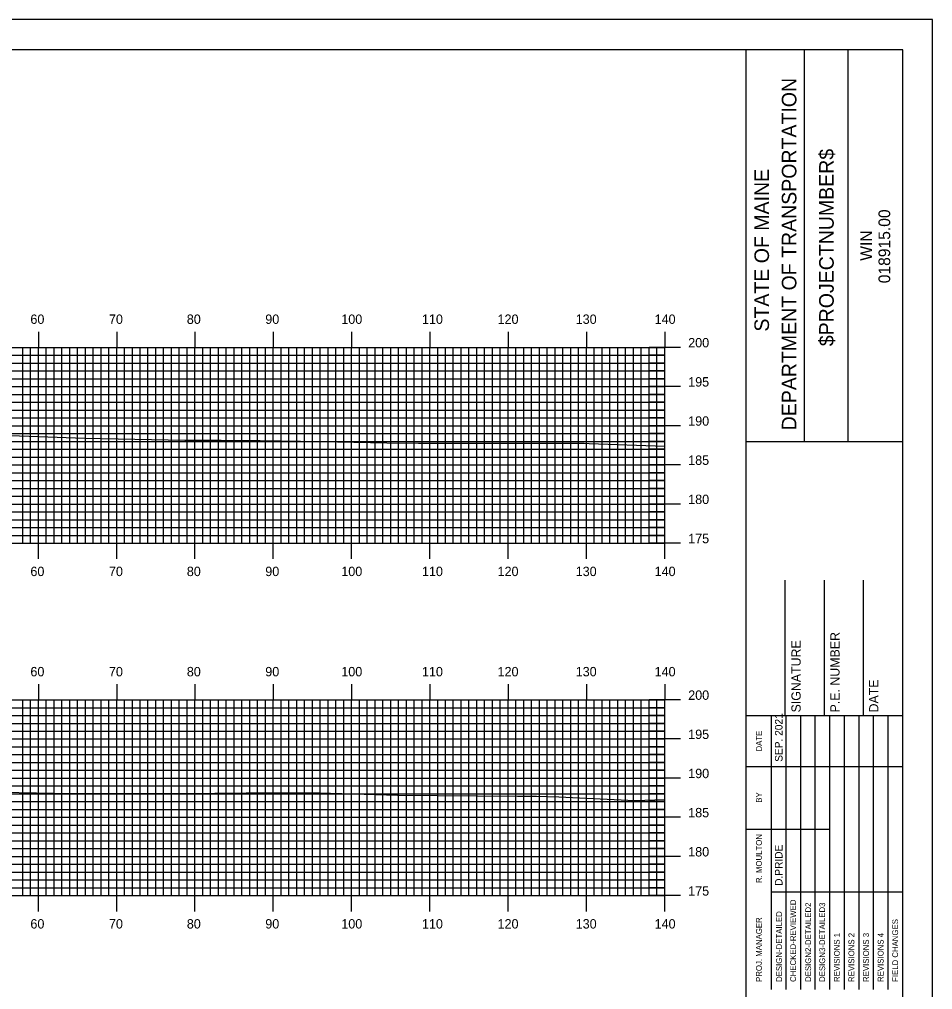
# Model space of a CAD drawing. Extents: x 1797601 to 1797944, y 442591 to 442811.
# Drawn here: x 1797824 to 1797940.7, y 442686.7 to 442810.5 of the extents above; entities that cross this region are included whole.
import ezdxf

# ---------------------------------------------------------------- set-up
doc = ezdxf.new("R2010")
doc.units = 0
for name, color, linetype in [('BORDER', 7, 'Continuous'), ('H_V ANNOTATION', 7, 'Continuous'), ('MAJOR', 7, 'Continuous'), ('MINOR', 7, 'Continuous'), ('PLOT BOUNDARY', 7, 'Continuous'), ('S_Roadway_Centerline', 7, 'Continuous')]:
    doc.layers.add(name, color=color, linetype=linetype)

msp = doc.modelspace()

# ---------------------------------------------------------------- linework, layer by layer
at = {"layer": 'BORDER'}
for p, q in [((1797916.84, 442596.67), (1797916.84, 442806.67)), ((1797924.3, 442756.66), (1797924.3, 442806.66)), ((1797929.89, 442756.66), (1797929.89, 442806.66)), ((1797916.85, 442756.65), (1797936.84, 442756.65)), ((1797921.84, 442721.67), (1797921.84, 442738.97)), ((1797926.84, 442721.67), (1797926.84, 442738.97)), ((1797931.84, 442721.67), (1797931.84, 442738.97)), ((1797916.84, 442721.67), (1797936.84, 442721.67))]:
    msp.add_line(p, q, dxfattribs=at)
msp.add_lwpolyline([(1797616.84, 442596.67), (1797936.84, 442596.67), (1797936.84, 442806.67), (1797616.84, 442806.67)], close=True, dxfattribs=at)
for points in [[(1797920.07, 442715.17), (1797920.07, 442721.67)], [(1797921.94, 442686.68), (1797921.94, 442721.67)], [(1797923.8, 442721.67), (1797923.8, 442686.68)], [(1797925.67, 442686.68), (1797925.67, 442721.67)], [(1797927.53, 442686.68), (1797927.53, 442721.67)], [(1797929.39, 442686.68), (1797929.39, 442721.67)], [(1797931.26, 442686.68), (1797931.26, 442721.67)], [(1797933.12, 442686.68), (1797933.12, 442721.67)], [(1797934.98, 442686.68), (1797934.98, 442721.67)], [(1797920.08, 442686.68), (1797920.08, 442720.26)], [(1797916.84, 442715.17), (1797936.84, 442715.17)], [(1797916.84, 442707.17), (1797920.08, 442707.17)], [(1797920.07, 442707.17), (1797927.53, 442707.17)], [(1797920.07, 442699.17), (1797936.84, 442699.17)]]:
    msp.add_lwpolyline(points, dxfattribs=at)
at = {"layer": 'MAJOR'}
for p, q in [((1797826.44, 442770.67), (1797826.44, 442768.67)), ((1797836.44, 442770.67), (1797836.44, 442768.67)), ((1797846.44, 442770.67), (1797846.44, 442768.67)), ((1797856.44, 442770.67), (1797856.44, 442768.67)), ((1797866.44, 442770.67), (1797866.44, 442768.67)), ((1797876.44, 442770.67), (1797876.44, 442768.67)), ((1797886.44, 442770.67), (1797886.44, 442768.67)), ((1797896.44, 442770.67), (1797896.44, 442768.67)), ((1797906.44, 442770.67), (1797906.44, 442768.67)), ((1797626.44, 442768.67), (1797906.44, 442768.67)), ((1797626.44, 442768.67), (1797906.44, 442768.67)), ((1797826.44, 442743.67), (1797826.44, 442768.67)), ((1797836.44, 442743.67), (1797836.44, 442768.67)), ((1797846.44, 442743.67), (1797846.44, 442768.67)), ((1797856.44, 442743.67), (1797856.44, 442768.67)), ((1797866.44, 442743.67), (1797866.44, 442768.67)), ((1797876.44, 442743.67), (1797876.44, 442768.67)), ((1797886.44, 442743.67), (1797886.44, 442768.67)), ((1797896.44, 442743.67), (1797896.44, 442768.67)), ((1797908.45, 442768.67), (1797904.44, 442768.67)), ((1797906.44, 442743.67), (1797906.44, 442768.67)), ((1797906.44, 442743.67), (1797906.44, 442768.67)), ((1797626.44, 442763.67), (1797906.44, 442763.67)), ((1797908.45, 442763.67), (1797904.44, 442763.67)), ((1797626.44, 442758.67), (1797906.44, 442758.67)), ((1797908.45, 442758.67), (1797904.44, 442758.67)), ((1797626.44, 442753.67), (1797906.44, 442753.67)), ((1797908.45, 442753.67), (1797904.44, 442753.67)), ((1797626.44, 442748.67), (1797906.44, 442748.67)), ((1797908.45, 442748.67), (1797904.44, 442748.67)), ((1797626.44, 442743.67), (1797906.44, 442743.67)), ((1797626.44, 442743.67), (1797906.44, 442743.67)), ((1797826.44, 442741.66), (1797826.44, 442743.67)), ((1797836.44, 442741.66), (1797836.44, 442743.67)), ((1797846.44, 442741.66), (1797846.44, 442743.67)), ((1797856.44, 442741.66), (1797856.44, 442743.67)), ((1797866.44, 442741.66), (1797866.44, 442743.67)), ((1797876.44, 442741.66), (1797876.44, 442743.67)), ((1797886.44, 442741.66), (1797886.44, 442743.67)), ((1797896.44, 442741.66), (1797896.44, 442743.67)), ((1797908.45, 442743.67), (1797904.44, 442743.67)), ((1797906.44, 442741.66), (1797906.44, 442743.67)), ((1797826.44, 442725.67), (1797826.44, 442723.67)), ((1797836.44, 442725.67), (1797836.44, 442723.67)), ((1797846.44, 442725.67), (1797846.44, 442723.67)), ((1797856.44, 442725.67), (1797856.44, 442723.67)), ((1797866.44, 442725.67), (1797866.44, 442723.67)), ((1797876.44, 442725.67), (1797876.44, 442723.67)), ((1797886.44, 442725.67), (1797886.44, 442723.67)), ((1797896.44, 442725.67), (1797896.44, 442723.67)), ((1797906.44, 442725.67), (1797906.44, 442723.67)), ((1797626.44, 442723.67), (1797906.44, 442723.67)), ((1797626.44, 442723.67), (1797906.44, 442723.67)), ((1797826.44, 442698.67), (1797826.44, 442723.67)), ((1797836.44, 442698.67), (1797836.44, 442723.67)), ((1797846.44, 442698.67), (1797846.44, 442723.67)), ((1797856.44, 442698.67), (1797856.44, 442723.67)), ((1797866.44, 442698.67), (1797866.44, 442723.67)), ((1797876.44, 442698.67), (1797876.44, 442723.67)), ((1797886.44, 442698.67), (1797886.44, 442723.67)), ((1797896.44, 442698.67), (1797896.44, 442723.67)), ((1797908.45, 442723.67), (1797904.44, 442723.67)), ((1797906.44, 442698.67), (1797906.44, 442723.67)), ((1797906.44, 442698.67), (1797906.44, 442723.67)), ((1797626.44, 442718.67), (1797906.44, 442718.67)), ((1797908.45, 442718.67), (1797904.44, 442718.67)), ((1797626.44, 442713.67), (1797906.44, 442713.67)), ((1797908.45, 442713.67), (1797904.44, 442713.67)), ((1797626.44, 442708.67), (1797906.44, 442708.67)), ((1797908.45, 442708.67), (1797904.44, 442708.67)), ((1797626.44, 442703.67), (1797906.44, 442703.67)), ((1797908.45, 442703.67), (1797904.44, 442703.67)), ((1797626.44, 442698.67), (1797906.44, 442698.67)), ((1797626.44, 442698.67), (1797906.44, 442698.67)), ((1797826.44, 442696.66), (1797826.44, 442698.67)), ((1797836.44, 442696.66), (1797836.44, 442698.67)), ((1797846.44, 442696.66), (1797846.44, 442698.67)), ((1797856.44, 442696.66), (1797856.44, 442698.67)), ((1797866.44, 442696.66), (1797866.44, 442698.67)), ((1797876.44, 442696.66), (1797876.44, 442698.67)), ((1797886.44, 442696.66), (1797886.44, 442698.67)), ((1797896.44, 442696.66), (1797896.44, 442698.67)), ((1797908.45, 442698.67), (1797904.44, 442698.67)), ((1797906.44, 442696.66), (1797906.44, 442698.67))]:
    msp.add_line(p, q, dxfattribs=at)
at = {"layer": 'MINOR'}
for p, q in [((1797824.44, 442743.67), (1797824.44, 442768.67)), ((1797825.44, 442743.67), (1797825.44, 442768.67)), ((1797827.44, 442743.67), (1797827.44, 442768.67)), ((1797828.44, 442743.67), (1797828.44, 442768.67)), ((1797829.44, 442743.67), (1797829.44, 442768.67)), ((1797830.44, 442743.67), (1797830.44, 442768.67)), ((1797831.44, 442743.67), (1797831.44, 442768.67)), ((1797832.44, 442743.67), (1797832.44, 442768.67)), ((1797833.44, 442743.67), (1797833.44, 442768.67)), ((1797834.44, 442743.67), (1797834.44, 442768.67)), ((1797835.44, 442743.67), (1797835.44, 442768.67)), ((1797837.44, 442743.67), (1797837.44, 442768.67)), ((1797838.44, 442743.67), (1797838.44, 442768.67)), ((1797839.44, 442743.67), (1797839.44, 442768.67)), ((1797840.44, 442743.67), (1797840.44, 442768.67)), ((1797841.44, 442743.67), (1797841.44, 442768.67)), ((1797842.44, 442743.67), (1797842.44, 442768.67)), ((1797843.44, 442743.67), (1797843.44, 442768.67)), ((1797844.44, 442743.67), (1797844.44, 442768.67)), ((1797845.44, 442743.67), (1797845.44, 442768.67)), ((1797847.44, 442743.67), (1797847.44, 442768.67)), ((1797848.44, 442743.67), (1797848.44, 442768.67)), ((1797849.44, 442743.67), (1797849.44, 442768.67)), ((1797850.44, 442743.67), (1797850.44, 442768.67)), ((1797851.44, 442743.67), (1797851.44, 442768.67)), ((1797852.44, 442743.67), (1797852.44, 442768.67)), ((1797853.44, 442743.67), (1797853.44, 442768.67)), ((1797854.44, 442743.67), (1797854.44, 442768.67)), ((1797855.44, 442743.67), (1797855.44, 442768.67)), ((1797857.44, 442743.67), (1797857.44, 442768.67)), ((1797858.44, 442743.67), (1797858.44, 442768.67)), ((1797859.44, 442743.67), (1797859.44, 442768.67)), ((1797860.44, 442743.67), (1797860.44, 442768.67)), ((1797861.44, 442743.67), (1797861.44, 442768.67)), ((1797862.44, 442743.67), (1797862.44, 442768.67)), ((1797863.44, 442743.67), (1797863.44, 442768.67)), ((1797864.44, 442743.67), (1797864.44, 442768.67)), ((1797865.44, 442743.67), (1797865.44, 442768.67)), ((1797867.44, 442743.67), (1797867.44, 442768.67)), ((1797868.44, 442743.67), (1797868.44, 442768.67)), ((1797869.44, 442743.67), (1797869.44, 442768.67)), ((1797870.44, 442743.67), (1797870.44, 442768.67)), ((1797871.44, 442743.67), (1797871.44, 442768.67)), ((1797872.44, 442743.67), (1797872.44, 442768.67)), ((1797873.44, 442743.67), (1797873.44, 442768.67)), ((1797874.44, 442743.67), (1797874.44, 442768.67)), ((1797875.44, 442743.67), (1797875.44, 442768.67)), ((1797877.44, 442743.67), (1797877.44, 442768.67)), ((1797878.44, 442743.67), (1797878.44, 442768.67)), ((1797879.44, 442743.67), (1797879.44, 442768.67)), ((1797880.44, 442743.67), (1797880.44, 442768.67)), ((1797881.44, 442743.67), (1797881.44, 442768.67)), ((1797882.44, 442743.67), (1797882.44, 442768.67)), ((1797883.44, 442743.67), (1797883.44, 442768.67)), ((1797884.44, 442743.67), (1797884.44, 442768.67)), ((1797885.44, 442743.67), (1797885.44, 442768.67)), ((1797887.44, 442743.67), (1797887.44, 442768.67)), ((1797888.44, 442743.67), (1797888.44, 442768.67)), ((1797889.44, 442743.67), (1797889.44, 442768.67)), ((1797890.44, 442743.67), (1797890.44, 442768.67)), ((1797891.44, 442743.67), (1797891.44, 442768.67)), ((1797892.44, 442743.67), (1797892.44, 442768.67)), ((1797893.44, 442743.67), (1797893.44, 442768.67)), ((1797894.44, 442743.67), (1797894.44, 442768.67)), ((1797895.44, 442743.67), (1797895.44, 442768.67)), ((1797897.44, 442743.67), (1797897.44, 442768.67)), ((1797898.44, 442743.67), (1797898.44, 442768.67)), ((1797899.44, 442743.67), (1797899.44, 442768.67)), ((1797900.44, 442743.67), (1797900.44, 442768.67)), ((1797901.44, 442743.67), (1797901.44, 442768.67)), ((1797902.44, 442743.67), (1797902.44, 442768.67)), ((1797903.44, 442743.67), (1797903.44, 442768.67)), ((1797904.44, 442743.67), (1797904.44, 442768.67)), ((1797905.44, 442743.67), (1797905.44, 442768.67)), ((1797626.44, 442767.67), (1797906.44, 442767.67)), ((1797906.44, 442767.67), (1797904.44, 442767.67)), ((1797626.44, 442766.67), (1797906.44, 442766.67)), ((1797906.44, 442766.67), (1797904.44, 442766.67)), ((1797626.44, 442765.67), (1797906.44, 442765.67)), ((1797906.44, 442765.67), (1797904.44, 442765.67)), ((1797626.44, 442764.67), (1797906.44, 442764.67)), ((1797906.44, 442764.67), (1797904.44, 442764.67)), ((1797626.44, 442762.67), (1797906.44, 442762.67)), ((1797906.44, 442762.67), (1797904.44, 442762.67)), ((1797626.44, 442761.67), (1797906.44, 442761.67)), ((1797906.44, 442761.67), (1797904.44, 442761.67)), ((1797626.44, 442760.67), (1797906.44, 442760.67)), ((1797906.44, 442760.67), (1797904.44, 442760.67)), ((1797626.44, 442759.67), (1797906.44, 442759.67)), ((1797906.44, 442759.67), (1797904.44, 442759.67)), ((1797626.44, 442757.67), (1797906.44, 442757.67)), ((1797906.44, 442757.67), (1797904.44, 442757.67)), ((1797626.44, 442756.67), (1797906.44, 442756.67)), ((1797906.44, 442756.67), (1797904.44, 442756.67)), ((1797626.44, 442755.67), (1797906.44, 442755.67)), ((1797906.44, 442755.67), (1797904.44, 442755.67)), ((1797626.44, 442754.67), (1797906.44, 442754.67)), ((1797906.44, 442754.67), (1797904.44, 442754.67)), ((1797626.44, 442752.67), (1797906.44, 442752.67)), ((1797906.44, 442752.67), (1797904.44, 442752.67)), ((1797626.44, 442751.67), (1797906.44, 442751.67)), ((1797906.44, 442751.67), (1797904.44, 442751.67)), ((1797626.44, 442750.67), (1797906.44, 442750.67)), ((1797906.44, 442750.67), (1797904.44, 442750.67)), ((1797626.44, 442749.67), (1797906.44, 442749.67)), ((1797906.44, 442749.67), (1797904.44, 442749.67)), ((1797626.44, 442747.67), (1797906.44, 442747.67)), ((1797906.44, 442747.67), (1797904.44, 442747.67)), ((1797626.44, 442746.67), (1797906.44, 442746.67)), ((1797906.44, 442746.67), (1797904.44, 442746.67)), ((1797626.44, 442745.67), (1797906.44, 442745.67)), ((1797906.44, 442745.67), (1797904.44, 442745.67)), ((1797626.44, 442744.67), (1797906.44, 442744.67)), ((1797906.44, 442744.67), (1797904.44, 442744.67)), ((1797824.44, 442698.67), (1797824.44, 442723.67)), ((1797825.44, 442698.67), (1797825.44, 442723.67)), ((1797827.44, 442698.67), (1797827.44, 442723.67)), ((1797828.44, 442698.67), (1797828.44, 442723.67)), ((1797829.44, 442698.67), (1797829.44, 442723.67)), ((1797830.44, 442698.67), (1797830.44, 442723.67)), ((1797831.44, 442698.67), (1797831.44, 442723.67)), ((1797832.44, 442698.67), (1797832.44, 442723.67)), ((1797833.44, 442698.67), (1797833.44, 442723.67)), ((1797834.44, 442698.67), (1797834.44, 442723.67)), ((1797835.44, 442698.67), (1797835.44, 442723.67)), ((1797837.44, 442698.67), (1797837.44, 442723.67)), ((1797838.44, 442698.67), (1797838.44, 442723.67)), ((1797839.44, 442698.67), (1797839.44, 442723.67)), ((1797840.44, 442698.67), (1797840.44, 442723.67)), ((1797841.44, 442698.67), (1797841.44, 442723.67)), ((1797842.44, 442698.67), (1797842.44, 442723.67)), ((1797843.44, 442698.67), (1797843.44, 442723.67)), ((1797844.44, 442698.67), (1797844.44, 442723.67)), ((1797845.44, 442698.67), (1797845.44, 442723.67)), ((1797847.44, 442698.67), (1797847.44, 442723.67)), ((1797848.44, 442698.67), (1797848.44, 442723.67)), ((1797849.44, 442698.67), (1797849.44, 442723.67)), ((1797850.44, 442698.67), (1797850.44, 442723.67)), ((1797851.44, 442698.67), (1797851.44, 442723.67)), ((1797852.44, 442698.67), (1797852.44, 442723.67)), ((1797853.44, 442698.67), (1797853.44, 442723.67)), ((1797854.44, 442698.67), (1797854.44, 442723.67)), ((1797855.44, 442698.67), (1797855.44, 442723.67)), ((1797857.44, 442698.67), (1797857.44, 442723.67)), ((1797858.44, 442698.67), (1797858.44, 442723.67)), ((1797859.44, 442698.67), (1797859.44, 442723.67)), ((1797860.44, 442698.67), (1797860.44, 442723.67)), ((1797861.44, 442698.67), (1797861.44, 442723.67)), ((1797862.44, 442698.67), (1797862.44, 442723.67)), ((1797863.44, 442698.67), (1797863.44, 442723.67)), ((1797864.44, 442698.67), (1797864.44, 442723.67)), ((1797865.44, 442698.67), (1797865.44, 442723.67)), ((1797867.44, 442698.67), (1797867.44, 442723.67)), ((1797868.44, 442698.67), (1797868.44, 442723.67)), ((1797869.44, 442698.67), (1797869.44, 442723.67)), ((1797870.44, 442698.67), (1797870.44, 442723.67)), ((1797871.44, 442698.67), (1797871.44, 442723.67)), ((1797872.44, 442698.67), (1797872.44, 442723.67)), ((1797873.44, 442698.67), (1797873.44, 442723.67)), ((1797874.44, 442698.67), (1797874.44, 442723.67)), ((1797875.44, 442698.67), (1797875.44, 442723.67)), ((1797877.44, 442698.67), (1797877.44, 442723.67)), ((1797878.44, 442698.67), (1797878.44, 442723.67)), ((1797879.44, 442698.67), (1797879.44, 442723.67)), ((1797880.44, 442698.67), (1797880.44, 442723.67)), ((1797881.44, 442698.67), (1797881.44, 442723.67)), ((1797882.44, 442698.67), (1797882.44, 442723.67)), ((1797883.44, 442698.67), (1797883.44, 442723.67)), ((1797884.44, 442698.67), (1797884.44, 442723.67)), ((1797885.44, 442698.67), (1797885.44, 442723.67)), ((1797887.44, 442698.67), (1797887.44, 442723.67)), ((1797888.44, 442698.67), (1797888.44, 442723.67)), ((1797889.44, 442698.67), (1797889.44, 442723.67)), ((1797890.44, 442698.67), (1797890.44, 442723.67)), ((1797891.44, 442698.67), (1797891.44, 442723.67)), ((1797892.44, 442698.67), (1797892.44, 442723.67)), ((1797893.44, 442698.67), (1797893.44, 442723.67)), ((1797894.44, 442698.67), (1797894.44, 442723.67)), ((1797895.44, 442698.67), (1797895.44, 442723.67)), ((1797897.44, 442698.67), (1797897.44, 442723.67)), ((1797898.44, 442698.67), (1797898.44, 442723.67)), ((1797899.44, 442698.67), (1797899.44, 442723.67)), ((1797900.44, 442698.67), (1797900.44, 442723.67)), ((1797901.44, 442698.67), (1797901.44, 442723.67)), ((1797902.44, 442698.67), (1797902.44, 442723.67)), ((1797903.44, 442698.67), (1797903.44, 442723.67)), ((1797904.44, 442698.67), (1797904.44, 442723.67)), ((1797905.44, 442698.67), (1797905.44, 442723.67)), ((1797626.44, 442722.67), (1797906.44, 442722.67)), ((1797626.44, 442721.67), (1797906.44, 442721.67)), ((1797906.44, 442722.67), (1797904.44, 442722.67)), ((1797906.44, 442721.67), (1797904.44, 442721.67)), ((1797626.44, 442720.67), (1797906.44, 442720.67)), ((1797906.44, 442720.67), (1797904.44, 442720.67)), ((1797626.44, 442719.67), (1797906.44, 442719.67)), ((1797906.44, 442719.67), (1797904.44, 442719.67)), ((1797626.44, 442717.67), (1797906.44, 442717.67)), ((1797626.44, 442716.67), (1797906.44, 442716.67)), ((1797906.44, 442717.67), (1797904.44, 442717.67)), ((1797906.44, 442716.67), (1797904.44, 442716.67)), ((1797626.44, 442715.67), (1797906.44, 442715.67)), ((1797906.44, 442715.67), (1797904.44, 442715.67)), ((1797626.44, 442714.67), (1797906.44, 442714.67)), ((1797906.44, 442714.67), (1797904.44, 442714.67)), ((1797626.44, 442712.67), (1797906.44, 442712.67)), ((1797626.44, 442711.67), (1797906.44, 442711.67)), ((1797906.44, 442712.67), (1797904.44, 442712.67)), ((1797906.44, 442711.67), (1797904.44, 442711.67)), ((1797626.44, 442710.67), (1797906.44, 442710.67)), ((1797906.44, 442710.67), (1797904.44, 442710.67)), ((1797626.44, 442709.67), (1797906.44, 442709.67)), ((1797906.44, 442709.67), (1797904.44, 442709.67)), ((1797626.44, 442707.67), (1797906.44, 442707.67)), ((1797626.44, 442706.67), (1797906.44, 442706.67)), ((1797906.44, 442707.67), (1797904.44, 442707.67)), ((1797906.44, 442706.67), (1797904.44, 442706.67)), ((1797626.44, 442705.67), (1797906.44, 442705.67)), ((1797906.44, 442705.67), (1797904.44, 442705.67)), ((1797626.44, 442704.67), (1797906.44, 442704.67)), ((1797906.44, 442704.67), (1797904.44, 442704.67)), ((1797626.44, 442702.67), (1797906.44, 442702.67)), ((1797626.44, 442701.67), (1797906.44, 442701.67)), ((1797906.44, 442702.67), (1797904.44, 442702.67)), ((1797906.44, 442701.67), (1797904.44, 442701.67)), ((1797626.44, 442700.67), (1797906.44, 442700.67)), ((1797906.44, 442700.67), (1797904.44, 442700.67)), ((1797626.44, 442699.67), (1797906.44, 442699.67)), ((1797906.44, 442699.67), (1797904.44, 442699.67))]:
    msp.add_line(p, q, dxfattribs=at)
at = {"layer": 'PLOT BOUNDARY'}
msp.add_lwpolyline([(1797600.66, 442590.55), (1797940.66, 442590.55), (1797940.66, 442810.55), (1797600.66, 442810.55)], close=True, dxfattribs=at)
at = {"layer": 'S_Roadway_Centerline'}
for points in [[(1797819.14, 442757.53), (1797826.47, 442757.28), (1797832.38, 442757.09), (1797845.15, 442756.83), (1797849.8, 442756.82), (1797854.75, 442756.79), (1797862.51, 442756.67), (1797870.95, 442756.49), (1797875.01, 442756.45), (1797891.86, 442756.44), (1797896.14, 442756.43), (1797896.77, 442756.41), (1797906.44, 442756.05)], [(1797821.72, 442711.89), (1797830.65, 442711.71), (1797835.61, 442711.72), (1797844.94, 442711.71), (1797853, 442711.8), (1797862.33, 442711.79), (1797872.32, 442711.49), (1797887.63, 442711.35), (1797890.08, 442711.39), (1797892.9, 442711.3), (1797902.63, 442710.81), (1797906.44, 442710.95)]]:
    msp.add_lwpolyline(points, dxfattribs=at)

# ---------------------------------------------------------------- texts
at = {"layer": 'BORDER'}
for s, height, p in [('DEPARTMENT OF TRANSPORTATION', 1.8635, (1797923.26, 442758.08)), ('$PROJECTNUMBER$', 1.8635, (1797928.03, 442768.82)), ('STATE OF MAINE', 1.8635, (1797919.76, 442770.69)), ('018915.00', 1.491, (1797935.24, 442776.86)), ('WIN', 1.491, (1797932.92, 442779.73)), ('P.E. NUMBER', 1.1811, (1797928.77, 442722.06)), ('SIGNATURE', 1.181, (1797923.81, 442722.06)), ('DATE', 1.181, (1797933.73, 442722.06)), ('SEP. 2021', 0.969, (1797921.49, 442715.76)), ('DATE', 0.743, (1797918.85, 442717.08)), ('BY', 0.743, (1797918.85, 442710.54)), ('R. MOULTON', 0.745, (1797918.85, 442700.28)), ('D.PRIDE', 0.969, (1797921.49, 442699.92)), ('CHECKED-REVIEWED', 0.7455, (1797923.21, 442687.65)), ('DESIGN2-DETAILED2', 0.7455, (1797925.14, 442687.65)), ('DESIGN3-DETAILED3', 0.7455, (1797926.93, 442687.65)), ('PROJ. MANAGER', 0.7455, (1797918.85, 442687.65)), ('DESIGN-DETAILED', 0.7455, (1797921.42, 442687.65)), ('FIELD CHANGES', 0.7455, (1797936.25, 442687.65)), ('REVISIONS 1', 0.7455, (1797928.8, 442687.65)), ('REVISIONS 2', 0.7455, (1797930.66, 442687.65)), ('REVISIONS 3', 0.7455, (1797932.52, 442687.65)), ('REVISIONS 4', 0.7455, (1797934.39, 442687.65))]:
    msp.add_text(s, height=height, rotation=90, dxfattribs=at).set_placement(p)
at = {"layer": 'H_V ANNOTATION'}
for s, p in [('60', (1797825.42, 442771.67)), ('70', (1797835.45, 442771.67)), ('80', (1797845.4, 442771.67)), ('90', (1797855.42, 442771.67)), ('100', (1797865.13, 442771.67)), ('110', (1797875.43, 442771.67)), ('120', (1797885.09, 442771.67)), ('130', (1797895.07, 442771.67)), ('140', (1797905.15, 442771.67)), ('200', (1797909.44, 442768.67)), ('195', (1797909.44, 442763.67)), ('190', (1797909.44, 442758.67)), ('185', (1797909.44, 442753.67)), ('180', (1797909.44, 442748.67)), ('175', (1797909.44, 442743.67)), ('60', (1797825.42, 442739.47)), ('70', (1797835.45, 442739.47)), ('80', (1797845.4, 442739.47)), ('90', (1797855.42, 442739.47)), ('100', (1797865.13, 442739.47)), ('110', (1797875.43, 442739.47)), ('120', (1797885.09, 442739.47)), ('130', (1797895.07, 442739.47)), ('140', (1797905.15, 442739.47)), ('60', (1797825.42, 442726.67)), ('70', (1797835.45, 442726.67)), ('80', (1797845.4, 442726.67)), ('90', (1797855.42, 442726.67)), ('100', (1797865.13, 442726.67)), ('110', (1797875.43, 442726.67)), ('120', (1797885.09, 442726.67)), ('130', (1797895.07, 442726.67)), ('140', (1797905.15, 442726.67)), ('200', (1797909.44, 442723.67)), ('195', (1797909.44, 442718.67)), ('190', (1797909.44, 442713.67)), ('185', (1797909.44, 442708.67)), ('180', (1797909.44, 442703.67)), ('175', (1797909.44, 442698.67)), ('60', (1797825.42, 442694.47)), ('70', (1797835.45, 442694.47)), ('80', (1797845.4, 442694.47)), ('90', (1797855.42, 442694.47)), ('100', (1797865.13, 442694.47)), ('110', (1797875.43, 442694.47)), ('120', (1797885.09, 442694.47)), ('130', (1797895.07, 442694.47)), ('140', (1797905.15, 442694.47))]:
    msp.add_text(s, height=1.2, dxfattribs=at).set_placement(p)

doc.saveas('drawing.dxf')
